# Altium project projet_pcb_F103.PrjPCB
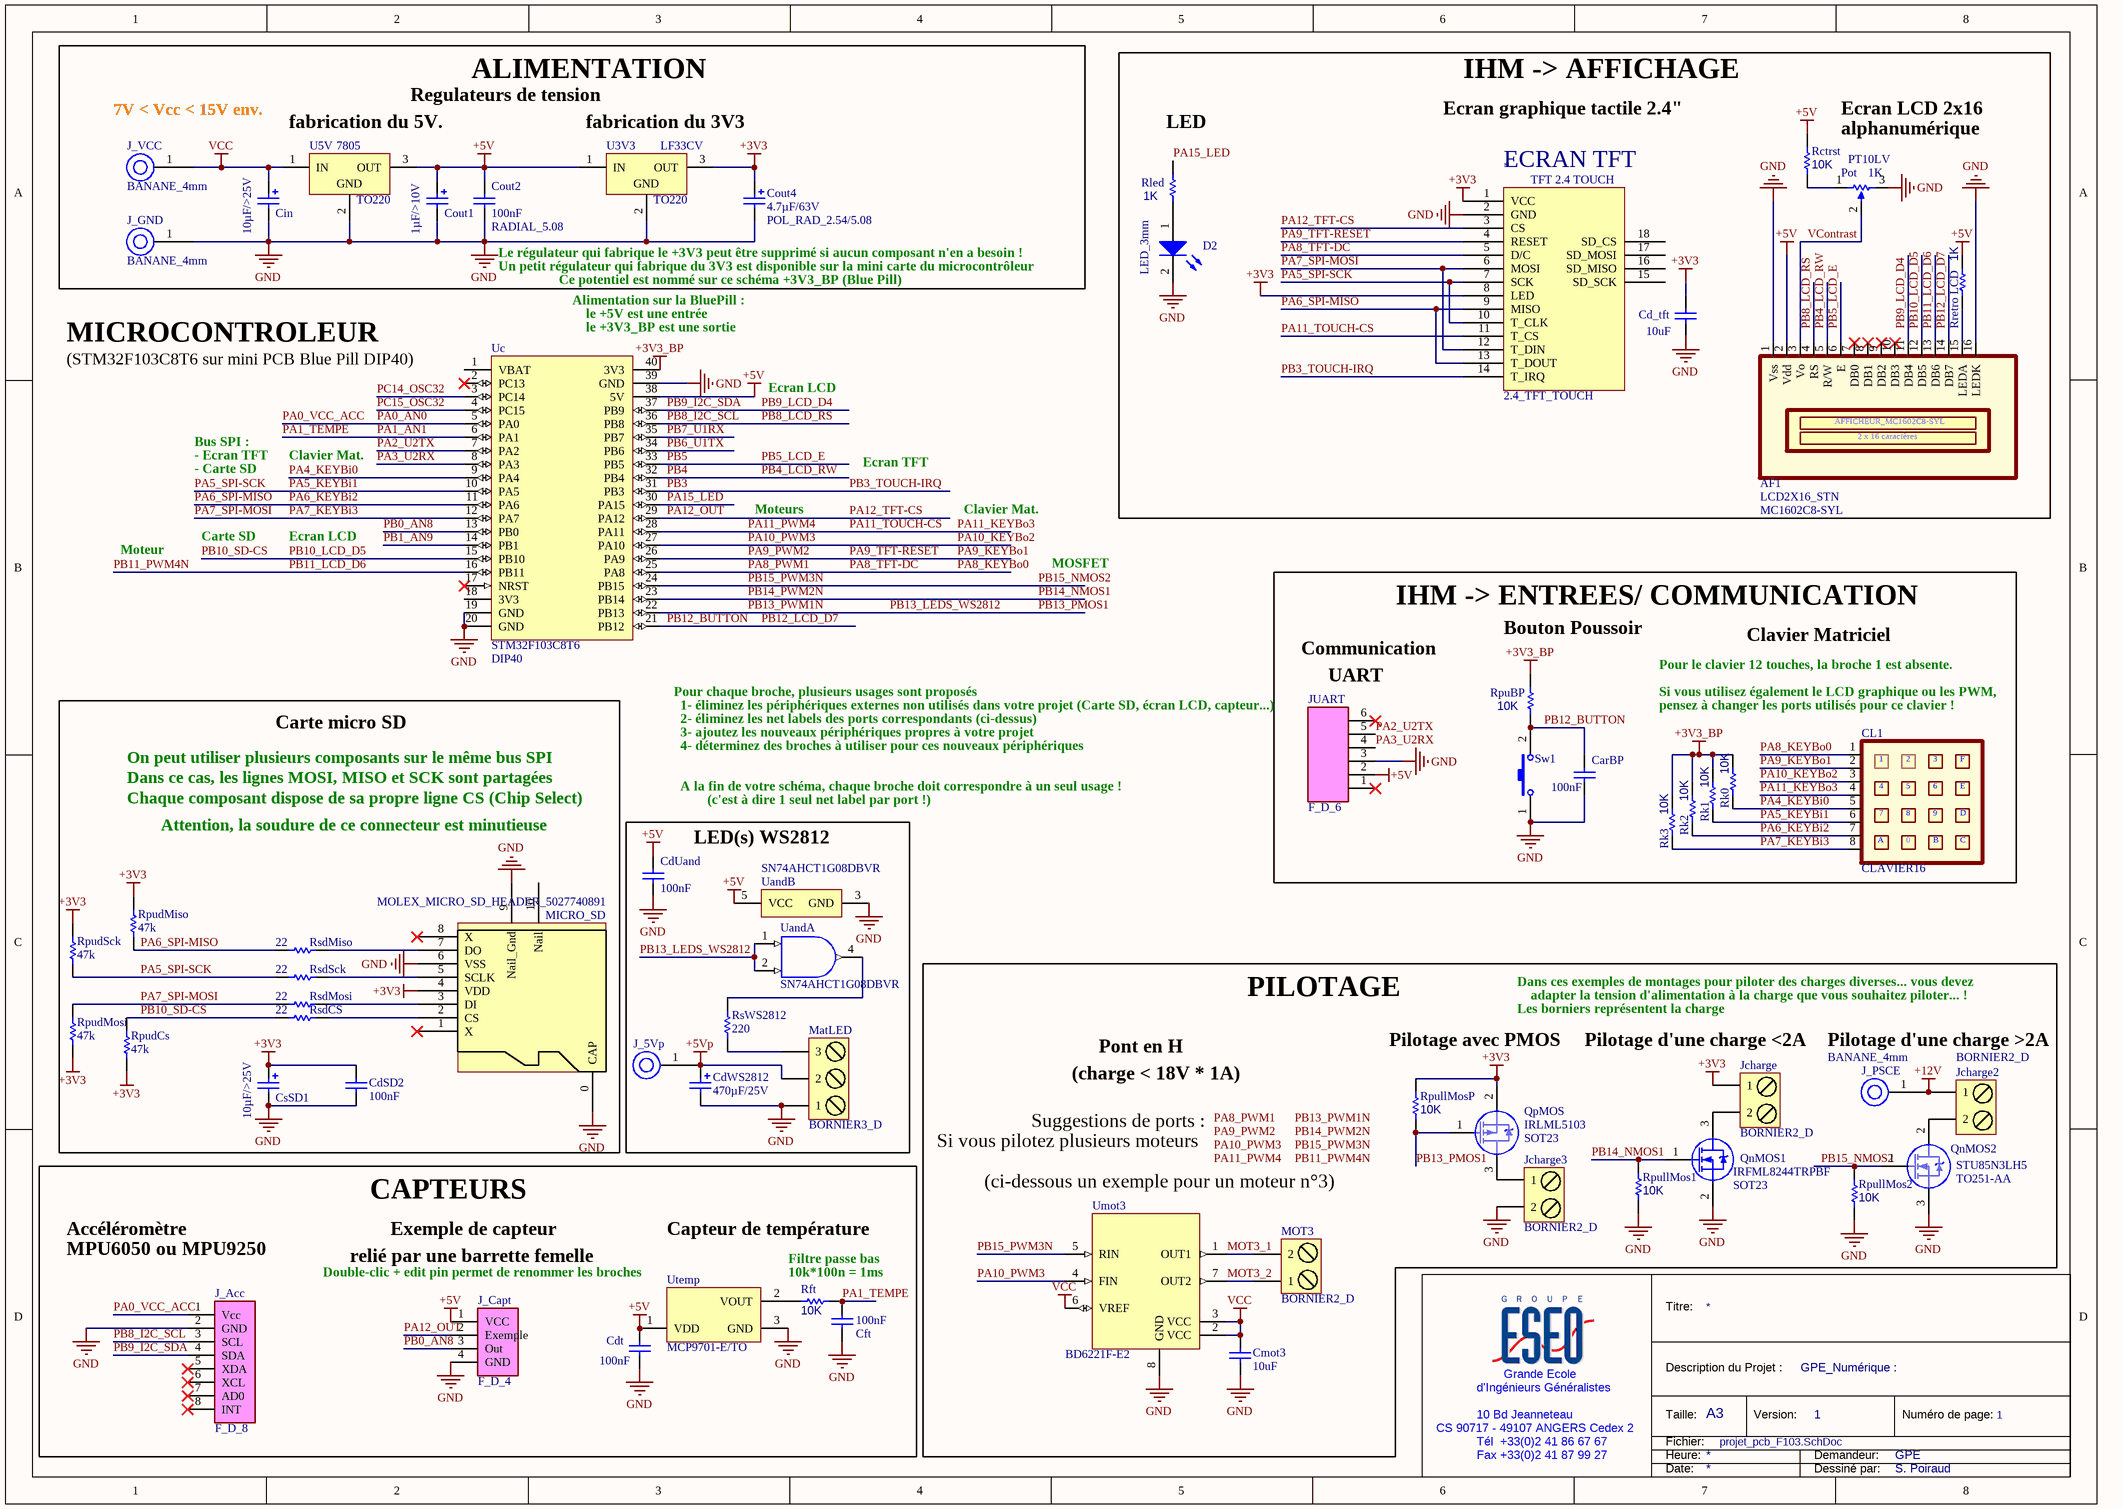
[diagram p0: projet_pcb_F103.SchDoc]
1 sheet, 62 parts. Net scope: global (net labels, ports and power ports of the same name join across sheets).
Board file: projet_pcb_F103.PCBDOC

## Sheet projet_pcb_F103.SchDoc
size A3

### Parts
*  2.4_TFT_TOUCH  [2.4_TFT_TOUCH]
AF1  Type: LCD2X16_STN  Name: MC1602C8-SYL  [AFFICHEUR_LCD_MC1602C8-SYL]  (hidden comment: AFFICHEUR_LCD_2X16_)
CarBP  value 100nF  [CONDENSATEUR_CERAMIQUE_RADIAL_5.08]  (hidden comment: CONDENSATEUR_CER_RAD_5.08)
Cd_tft  10uF  [CONDENSATEUR_POLARISE_ELECTROLYTIQUE_RADIAL_2.54/5.08]
CdSD2  100nF  [CONDENSATEUR_CERAMIQUE_RADIAL_5.08]
Cdt  value 100nF  [CONDENSATEUR_CERAMIQUE_RADIAL_5.08]  (hidden comment: CONDENSATEUR_CER_RAD_5.08)
CdUand  value 100nF  [CONDENSATEUR_CERAMIQUE_RADIAL_5.08]  (hidden comment: CONDENSATEUR_CER_RAD_5.08)
CdWS2812  value 470µF/25V  [CONDENSATEUR_POLARISE_ELECTROLYTIQUE_RADIAL_5.08/10.16]  (hidden comment: CONDENSATEUR_POL_ELECTROLY_RAD_5.08/10.16)
Cft  value 100nF  [CONDENSATEUR_CERAMIQUE_RADIAL_5.08]  (hidden comment: CONDENSATEUR_CER_RAD_5.08)
Cin  value 10µF/>25V  [CONDENSATEUR_POLARISE_ELECTROLYTIQUE_RADIAL_2.0/5.08]  (hidden comment: CONDENSATEUR_POL_ELECTROLY_RAD_2.0/5.08)
CL1  Type: CLAVIER16  [CLAVIER_16_TOUCHES]  (hidden comment: CLAVIER_16_TOUCHES)
Cmot3  10uF  [CONDENSATEUR_POLARISE_ELECTROLYTIQUE_RADIAL_2.0/5.08]
Cout1  value 1µF/>10V  [CONDENSATEUR_POLARISE_ELECTROLYTIQUE_RADIAL_2.0/5.08]  (hidden comment: CONDENSATEUR_POL_ELECTROLY_RAD_2.0/5.08)
Cout2  value 100nF  Type: RADIAL_5.08  [CONDENSATEUR_CERAMIQUE_RADIAL_5.08]  (hidden comment: CONDENSATEUR_CER_RAD_5.08)
Cout4  value 4.7µF/63V  Type: POL_RAD_2.54/5.08  [CONDENSATEUR_POLARISE_ELECTROLYTIQUE_RADIAL_2.54/5.08]  (hidden comment: CONDENSATEUR_POL_ELECTROLY_RAD_2.54/5.08)
CsSD1  value 10µF/>25V  [CONDENSATEUR_POLARISE_ELECTROLYTIQUE_RADIAL_2.0/5.08]  (hidden comment: CONDENSATEUR_POL_ELECTROLY_RAD_2.0/5.08)
D2  LED_3MM  [LED_3MM]
J_5Vp  DOUILLE BANANE 4mm  [DOUILLE_BANANE_4mm]  (value not drawn)
J_Acc  Type: F_D_8  [BARRETTE_8_F_D]  (hidden comment: BARRETTE_8 CONTACTS_1 RANGEE_FEMELLE_DROITE)
J_Capt  Type: F_D_4  [BARRETTE_4_F_D]  (hidden comment: BARRETTE_4 CONTACTS_1 RANGEE_FEMELLE_DROITE)
J_GND  Type: BANANE_4mm  [DOUILLE_BANANE_4mm]  (hidden comment: DOUILLE BANANE 4mm)
J_PSCE  Type: BANANE_4mm  [DOUILLE_BANANE_4mm]  (hidden comment: DOUILLE BANANE 4mm)
J_VCC  Type: BANANE_4mm  [DOUILLE_BANANE_4mm]  (hidden comment: DOUILLE BANANE 4mm)
Jcharge  Type: BORNIER2_D  [BORNIER2_A_VIS]  (hidden comment: BORNIER2 DROIT A VIS)
Jcharge2  Type: BORNIER2_D  [BORNIER2_A_VIS]  (hidden comment: BORNIER2 DROIT A VIS)
Jcharge3  Type: BORNIER2_D  [BORNIER2_A_VIS]  (hidden comment: BORNIER2 DROIT A VIS)
JUART  Type: F_D_6  [BARRETTE_6_F_D]  (hidden comment: BARRETTE_6 CONTACTS_1 RANGEE_FEMELLE_DROITE)
MatLED  Type: BORNIER3_D  [BORNIER3_A_VIS]  (hidden comment: BORNIER3 DROIT A VIS)
MICRO_SD  MOLEX_MICRO_SD_HEADER_5027740891  [MOLEX_MICRO_SD_HEADER_5027740891]
MOT3  Type: BORNIER2_D  [BORNIER2_A_VIS]  (hidden comment: BORNIER2 DROIT A VIS)
Pot  value 1K  Type: PT10LV  [TRIMMER_MONOTOUR_PT10LV]  (hidden comment: RESISTANCE_VARIABLE_TRAVERSANTE : PT10LV)
QnMOS1  Type: IRFML8244TRPBF  Package: SOT23  [TRANSISTOR_MOSFET-N_SOT23_GSD]  (hidden comment: TRANSISTOR_MOSFET-N_SOT23_GSD)
QnMOS2  Package: TO251-AA  [BARRETTE_3_F_D]  (hidden comment: TRANSISTOR_MOSFET-N_TO220_GDS)
QpMOS  Package: SOT23  Type: IRLML5103  [TRANSISTOR_MOSFET-P_SOT23_GSD]  (hidden comment: TRANSISTOR_MOSFET-P_SOT23_GSD)
Rctrst  value 10K  [RESISTANCE_1/4W]  (hidden comment: RESISTANCE_AXIALE_1/4W)
Rft  value 10K  [RESISTANCE_1/4W]  (hidden comment: RESISTANCE_AXIALE_1/4W)
Rk0  value 10K  [RESISTANCE_1/4W]  (hidden comment: RESISTANCE_AXIALE_1/4W)
Rk1  value 10K  [RESISTANCE_1/4W]  (hidden comment: RESISTANCE_AXIALE_1/4W)
Rk2  value 10K  [RESISTANCE_1/4W]  (hidden comment: RESISTANCE_AXIALE_1/4W)
Rk3  value 10K  [RESISTANCE_1/4W]  (hidden comment: RESISTANCE_AXIALE_1/4W)
Rled  value 1K  [RESISTANCE_1/4W]  (hidden comment: RESISTANCE_AXIALE_1/4W)
RpuBP  value 10K  [RESISTANCE_1/4W]  (hidden comment: RESISTANCE_AXIALE_1/4W)
RpudCs  47k  [RESISTANCE_1/4W]
RpudMiso  47k  [RESISTANCE_1/4W]
RpudMosi  47k  [RESISTANCE_1/4W]
RpudSck  47k  [RESISTANCE_1/4W]
RpullMos1  value 10K  [RESISTANCE_1/4W]  (hidden comment: RESISTANCE_AXIALE_1/4W)
RpullMos2  value 10K  [RESISTANCE_1/4W]  (hidden comment: RESISTANCE_AXIALE_1/4W)
RpullMosP  value 10K  [RESISTANCE_1/4W]  (hidden comment: RESISTANCE_AXIALE_1/4W)
Rretro_LCD  value 1K  [RESISTANCE_1/4W]  (hidden comment: RESISTANCE_AXIALE_1/4W)
RsdCS  22  [RESISTANCE_1/4W]
RsdMiso  22  [RESISTANCE_1/4W]
RsdMosi  22  [RESISTANCE_1/4W]
RsdSck  22  [RESISTANCE_1/4W]
RsWS2812  220  [RESISTANCE_1/4W]
Sw1  BOUTON_POUSSOIR_MINIATURE_TRAVERSANT  [BOUTON_POUSSE_PLAT_6x6]  (value not drawn)
U3V3  Type: LF33CV  Package: TO220  [REGULATEUR_TO220_78XX]  (hidden comment: REGULATEUR_TO220_78XX)
U5V  Type: 7805  Package: TO220  [REGULATEUR_TO220_78XX]  (hidden comment: REGULATEUR_TO220_78XX)
Uand  SN74AHCT1G08DBVR  [DBV0005A_N]  (parts A,B of 2)
Uc  Type: STM32F103C8T6  Package: DIP40  [STM32F103C8T6_DIP40]  (hidden comment: STM32F103C8T6/PCB_DIP40)
Umot3  BD6221F-E2  [SOIC8_PAS=1.27_LARG=4_LONG=5]
Utemp  Type: MCP9701-E/TO  [COMPOSANT_TO92]  (hidden comment: CAPTEUR_TEMPERATURE_MCP9701-E/TO)

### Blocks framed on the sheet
ALIMENTATION: Cin Cout1 Cout2 Cout4 J_GND J_VCC U3V3 U5V
IHM -> AFFICHAGE: * AF1 Cd_tft D2 Pot Rctrst Rled Rretro_LCD
IHM -> ENTREES/ COMMUNICATION: CarBP CL1 JUART Rk0-Rk3 RpuBP Sw1
Carte micro SD: CdSD2 CsSD1 MICRO_SD RpudCs RpudMiso RpudMosi RpudSck RsdCS RsdMiso RsdMosi RsdSck
LED(s) WS2812: CdUand CdWS2812 J_5Vp MatLED RsWS2812 Uand
PILOTAGE: Cmot3 J_PSCE Jcharge Jcharge2 Jcharge3 MOT3 QnMOS1 QnMOS2 QpMOS RpullMos1 RpullMos2 RpullMosP Umot3
CAPTEURS: Cdt Cft J_Acc J_Capt Rft Utemp

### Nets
+3V3: *.1(VCC) *.8(LED) Cd_tft.1 CdSD2.2 Cout4.1 CsSD1.1 Jcharge.1 MICRO_SD.4(VDD) QpMOS.2(S) RpudCs.1 RpudMiso.2 RpudMosi.1 RpudSck.2 RpullMosP.2 U3V3.3(OUT)
+3V3_BP: Rk0.2 Rk1.2 Rk2.2 Rk3.2 RpuBP.1 Uc.40(3V3)
+5V: AF1.2(Vdd) Cdt.1 CdUand.2 Cout1.1 Cout2.2 J_Capt.1(VCC) JUART.2 Rctrst.1 Rretro_LCD.1 U3V3.1(IN) U5V.3(OUT) Uand.5(VCC) Uc.38(5V) Utemp.1(VDD)
+5Vp: CdWS2812.1 J_5Vp.1 MatLED.2
+12V: J_PSCE.1 Jcharge2.1
GND: *.2(GND) AF1.1(Vss) AF1.16(LEDK) CarBP.1 Cd_tft.2 CdSD2.1 Cdt.2 CdUand.1 CdWS2812.2 Cft.2 Cin.2 Cmot3.1 Cout1.2 Cout2.1 Cout4.2 CsSD1.2 D2.2 J_Acc.2(GND) J_Capt.4(GND) J_GND.1 Jcharge3.2 JUART.3 MatLED.1 MICRO_SD.0(CAP) MICRO_SD.6(VSS) MICRO_SD.9(Nail_Gnd) Pot.3 QnMOS1.2(S) QnMOS2.3(S) RpullMos1.1 RpullMos2.1 Sw1.1 U3V3.2(GND) U5V.2(GND) Uand.3(GND) Uc.19(GND) Uc.20(GND) Uc.39(GND) Umot3.8(GND) Utemp.3(GND)
VCC: Cin.1 Cmot3.2 J_VCC.1 U5V.1(IN) Umot3.2(VCC) Umot3.3(VCC) Umot3.6(VREF)
MOT3_1: MOT3.2 Umot3.1(OUT1)
MOT3_2: MOT3.1 Umot3.7(OUT2)
PA0_AN0: J_Acc.1(Vcc) Uc.5(PA0)  [also labelled PA0_VCC_ACC]
PA1_AN1: Cft.1 Rft.2 Uc.6(PA1)  [also labelled PA1_TEMPE]
PA2_U2TX: JUART.5 Uc.7(PA2)
PA3_U2RX: JUART.4 Uc.8(PA3)
PA4_KEYBi0: CL1.5 Rk0.1 Uc.9(PA4)
PA5_KEYBi1: *.7(SCK) *.10(T_CLK) CL1.6 Rk1.1 RpudSck.1 RsdSck.1 Uc.10(PA5)  [also labelled PA5_SPI-SCK]
PA6_KEYBi2: *.9(MISO) *.13(T_DOUT) CL1.7 Rk2.1 RpudMiso.1 RsdMiso.1 Uc.11(PA6)  [also labelled PA6_SPI-MISO]
PA7_KEYBi3: *.6(MOSI) *.12(T_DIN) CL1.8 Rk3.1 RpudMosi.2 RsdMosi.1 Uc.12(PA7)  [also labelled PA7_SPI-MOSI]
PA8_KEYBo0: *.5(D/C) CL1.1 Uc.25(PA8)  [also labelled PA8_PWM1, PA8_TFT-DC]
PA9_KEYBo1: *.4(RESET) CL1.2 Uc.26(PA9)  [also labelled PA9_PWM2, PA9_TFT-RESET]
PA10_KEYBo2: CL1.3 Uc.27(PA10) Umot3.4(FIN)  [also labelled PA10_PWM3]
PA11_KEYBo3: *.11(T_CS) CL1.4 Uc.28(PA11)  [also labelled PA11_PWM4, PA11_TOUCH-CS]
PA12_OUT: *.3(CS) J_Capt.2(Exemple) Uc.29(PA12)  [also labelled PA12_TFT-CS]
PA15_LED: Rled.1 Uc.30(PA15)
PB0_AN8: J_Capt.3(Out) Uc.13(PB0)
PB1_AN9: Uc.14(PB1)
PB3: *.14(T_IRQ) Uc.31(PB3)  [also labelled PB3_TOUCH-IRQ]
PB4: AF1.5(R/W) Uc.32(PB4)  [also labelled PB4_LCD_RW]
PB5: AF1.6(E) Uc.33(PB5)  [also labelled PB5_LCD_E]
PB6_U1TX: Uc.34(PB6)
PB7_U1RX: Uc.35(PB7)
PB8_I2C_SCL: AF1.4(RS) J_Acc.3(SCL) Uc.36(PB8)  [also labelled PB8_LCD_RS]
PB9_I2C_SDA: AF1.11(DB4) J_Acc.4(SDA) Uc.37(PB9)  [also labelled PB9_LCD_D4]
PB10_LCD_D5: AF1.12(DB5) RpudCs.2 RsdCS.1 Uc.15(PB10)  [also labelled PB10_SD-CS]
PB11_LCD_D6: AF1.13(DB6) Uc.16(PB11)  [also labelled PB11_PWM4N]
PB12_BUTTON: AF1.14(DB7) CarBP.2 RpuBP.2 Sw1.2 Uc.21(PB12)  [also labelled PB12_LCD_D7]
PB13_LEDS_WS2812: QpMOS.1(G) RpullMosP.1 Uand.1(A) Uand.2(B) Uc.22(PB13)  [also labelled PB13_PMOS1, PB13_PWM1N]
PB14_NMOS1: QnMOS1.1(G) RpullMos1.2 Uc.23(PB14)  [also labelled PB14_PWM2N]
PB15_NMOS2: QnMOS2.1(G) RpullMos2.2 Uc.24(PB15) Umot3.5(RIN)  [also labelled PB15_PWM3N]
PC14_OSC32: Uc.3(PC14)
PC15_OSC32: Uc.4(PC15)
VContrast: AF1.3(Vo) Pot.2
NetAF1_15: AF1.15(LEDA) Rretro_LCD.2
NetD2_1: D2.1 Rled.2
NetJcharge2_2: Jcharge2.2 QnMOS2.2(D)
NetJcharge3_1: Jcharge3.1 QpMOS.3(D)
NetJcharge_2: Jcharge.2 QnMOS1.3(D)
NetMatLED_3: MatLED.3 RsWS2812.1
NetMICRO_SD_2: MICRO_SD.2(CS) RsdCS.2
NetMICRO_SD_3: MICRO_SD.3(DI) RsdMosi.2
NetMICRO_SD_5: MICRO_SD.5(SCLK) RsdSck.2
NetMICRO_SD_7: MICRO_SD.7(DO) RsdMiso.2
NetPot_1: Pot.1 Rctrst.2
NetRft_1: Rft.1 Utemp.2(VOUT)
NetRsWS2812_2: RsWS2812.2 Uand.4(Y)

Not connected (* = marked no-connect by the designer): * 15(SD_SCK) 16(SD_MISO) 17(SD_MOSI) 18(SD_CS); AF1 7(DB0)* 8(DB1)* 9(DB2)* 10(DB3)*; J_Acc 5(XDA)* 6(XCL)* 7(AD0)* 8(INT)*; JUART 1* 6*; MICRO_SD 1(X)* 8(X)* 10(Nail); Uc 1(VBAT) 2(PC13)* 17(NRST)* 18(3V3)

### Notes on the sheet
- Regulateurs de tension
- 7V < Vcc < 15V env.
- (near U5V) fabrication du 5V.
- (near U3V3) fabrication du 3V3
- (near Rled) LED
- Ecran graphique tactile 2.4"
- (near *) ECRAN TFT
- Ecran LCD 2x16
- alphanumérique
- Le régulateur qui fabrique le +3V3 peut être supprimé si aucun composant n'en a besoin !
- Un petit régulateur qui fabrique du 3V3 est disponible sur la mini carte du microcontrôleur
- Ce potentiel est nommé sur ce schéma +3V3_BP (Blue Pill)
- Alimentation sur la BluePill :
- (near Uc) le +5V est une entrée
- MICROCONTROLEUR
- (near Uc) (STM32F103C8T6 sur mini PCB Blue Pill DIP40)
- (near Uc) le +3V3_BP est une sortie
- Bus SPI :
- Ecran LCD
- - Ecran TFT
- - Carte SD
- Clavier Mat.
- Moteurs
- Ecran TFT
- Moteur
- Carte SD
- MOSFET
- (near RpuBP) Bouton Poussoir
- Clavier Matriciel
- Pour chaque broche, plusieurs usages sont proposés
- (near JUART) 1- éliminez les périphériques externes non utilisés dans votre projet (Carte SD, écran LCD, capteur...)
- 2- éliminez les net labels des ports correspondants (ci-dessus)
- Communication
- (near JUART) UART
- Pour le clavier 12 touches, la broche 1 est absente.
- Si vous utilisez également le LCD graphique ou les PWM,
- pensez à changer les ports utilisés pour ce clavier !
- On peut utiliser plusieurs composants sur le même bus SPI
- Dans ce cas, les lignes MOSI, MISO et SCK sont partagées
- 3- ajoutez les nouveaux périphériques propres à votre projet
- 4- déterminez des broches à utiliser pour ces nouveaux périphériques
- Chaque composant dispose de sa propre ligne CS (Chip Select)
- Attention, la soudure de ce connecteur est minutieuse
- A la fin de votre schéma, chaque broche doit correspondre à un seul usage !
- (c'est à dire 1 seul net label par port !)
- Dans ces exemples de montages pour piloter des charges diverses... vous devez
- Pont en H
- Pilotage avec PMOS
- Les borniers représentent la charge
- adapter la tension d'alimentation à la charge que vous souhaitez piloter... !
- (near Jcharge) Pilotage d'une charge <2A
- Pilotage d'une charge >2A
- Suggestions de ports :
- (charge < 18V * 1A)
- Si vous pilotez plusieurs moteurs
- (ci-dessous un exemple pour un moteur n°3)
- STU85N3LH5
- Accéléromètre
- MPU6050 ou MPU9250
- relié par une barrette femelle
- Exemple de capteur
- Capteur de température
- Filtre passe bas
- (near Utemp) Double-clic + edit pin permet de renommer les broches
- 10k*100n = 1ms
- Titre:
- d'Ingénieurs Généralistes
- Grande Ecole
- Description du Projet :
- GPE_Numérique :
- CS 90717 - 49107 ANGERS Cedex 2
- 10 Bd Jeanneteau
- Tél  +33(0)2 41 86 67 67
- Fax +33(0)2 41 87 99 27
- Taille:
- Heure:
- Fichier:
- A3
- Version:
- 1
- Demandeur:
- GPE
- Numéro de page:
- Date:
- Dessiné par:
- S. Poiraud
- Labels drawn without touching a wire or pin: PA8_PWM1, PA9_PWM2, PA10_PWM3, PA11_PWM4, PB11_PWM4N, PB13_PWM1N, PB14_PWM2N, PB15_PWM3N

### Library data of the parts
AF1 = AFFICHEUR_LCD_MC1602C8-SYL: AFFICHEUR LCD - 2x16 LIGNES - 5X7 DOTS - STN - 80mm x 36mm
CarBP Cdt CdUand Cft Cout2 = CONDENSATEUR_CER_RAD_5.08: CONDENSATEUR TRAVERSANT CERAMIQUE RADIAL 5.08mm
Cd_tft CdSD2 Cmot3 = Condensateur: Capacitor
CdWS2812 = CONDENSATEUR_POL_ELECTROLY_RAD_5.08/10.16: CONDENSATEUR POLARISE ELECTROLYTIQUE RADIAL 5.08/10.16
Cin Cout1 CsSD1 = CONDENSATEUR_POL_ELECTROLY_RAD_2.0/5.08: CONDENSATEUR POLARISE ELECTROLYTIQUE RADIAL 2.0/5.08
CL1 = CLAVIER_16_TOUCHES: CLAVIER 16 TOUCHES
Cout4 = CONDENSATEUR_POL_ELECTROLY_RAD_2.54/5.08: CONDENSATEUR POLARISE ELECTROLYTIQUE RADIAL 2.54/5.08
D2 = LED_3MM: LED 3MM - ROUGE/VERTE/JAUNE
J_5Vp J_GND J_PSCE J_VCC = DOUILLE_BANANE_4mm: DOUILLE BANANE 4 mm
J_Capt = BARRETTE_4 CONTACTS_1 RANGEE_FEMELLE_DROITE: BARRETTE 4 CONTACTS 1 RANGEE FEMELLE DROITE
Jcharge Jcharge2 Jcharge3 MOT3 = BORNIER2_DROIT_A VIS: BORNIER 2 PLOTS DROIT A VIS 5.08mm
JUART = BARRETTE_6 CONTACTS_1 RANGEE_FEMELLE_DROITE: BARRETTE 6 CONTACTS 1 RANGEE FEMELLE DROITE
MatLED = BORNIER3_DROIT_A VIS: BORNIER 3 PLOTS DROIT A VIS 5.08mm
Pot = RESISTANCE_VARIABLE_TRAVERSANTE : PT10LV: RESISTANCE VARIABLE_TRAVERSANTE : PT10LV
QnMOS1 = TRANSISTOR_MOSFET-N_SOT23_GSD: TRANSISTOR MOSFET CANAL N BOITIER SOT23_GSD
QnMOS2 = TRANSISTOR_MOSFET-N_TO220_GDS: TRANSISTOR MOSFET CANAL N BOITIER TO220_GDS
QpMOS = TRANSISTOR_MOSFET-P_SOT23_GSD: TRANSISTOR MOSFET CANAL P BOITIER SOT23_GSD
Rctrst Rft Rk0-Rk3 Rled RpuBP RpullMos1 RpullMos2 RpullMosP Rretro_LCD = RESISTANCE_AXIALE_1/4W: RESISTANCE TRAVERSANTE AXIALE 1/4W
RpudCs RpudMiso RpudMosi RpudSck RsdCS RsdMiso RsdMosi RsdSck RsWS2812 = Resistor
Sw1 = BOUTON_POUSSOIR_MINIATURE_TRAVERSANT: BOUTON POUSSOIR MINIATURE TRAVERSANT ON/OFF
U3V3 U5V = REGULATEUR_TO220_78XX: REGULATEUR DE TENSION POSITIVE 78XX BOITIER TO220
Uand = SN74AHCT1G08DBVR: Single 2-Input Positive-AND Gate, DBV0005A, LARGE T&R; Manufacturer: Texas Instruments; VCC(Min)(V): 2; VCC(Max)(V): 5.5; Output Type: CMOS; ICC @ Nom Voltage(Max)(mA): 0.01; Bits(#): 1; F @ Nom Voltage(Max)(Mhz): 75; Rating: Catalog; Technology Family: AHCT; Voltage(Nom)(V): 5; Schmitt Trigger: No; Output Drive (IOL/IOH)(Max)(mA): 8/-8; tpd @ Nom Voltage(Max)(ns): 7.1; Logic: True; Gate Type: AND
Uc = STM32F103C8T6/PCB_DIP40: MICROCONTROLEUR 32 BITS - 72MHz - 34 I/O - 64 KO : FLASH - 20KO RAM - 10 CANAUX A/D 12 BITS - DIP40 - UART, SPI, I2C, USB, CAN
Umot3 = BD6220F: H Bridge - 2A
Utemp = CAPTEUR_TEMPERATURE_MCP9701-E/TO: CAPTEUR DE TEMPERATURE ANALOGIQUE LINEAIRE - TO92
